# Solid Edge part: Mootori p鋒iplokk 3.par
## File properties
Author: KULL
Template: Iso Metric Part.par
Last saved by: KULL
Revision: 72
Application: Solid Edge
Density: 6920,000 kg/m^3
Accuracy: 0,990
Material: Iron, grey cast type 60
Face Style: Gray
Fill Style: ANSI31(Iron)
Virtual Style: ANSI31(Iron)
Categorization: Metals\Iron
LibraryName: Materials
Coef. of Thermal Exp: 1.1e-05
Thermal Conductivity: 48.0
Specific Heat: 544.0
Modulus of Elasticity: 158579411000.0
Poisson's Ratio: 0.29
Yield Stress: 275790291.72673446
Ultimate Stress: 413685437.59010166
Elongation: 0.0
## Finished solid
Body 1: sheet body, 1 face, 44 edges, 44 vertices.
  Faces by surface: plane 1
  Edges by curve: line 36, circle 8
Body 2: sheet body, 3 faces, 44 edges, 44 vertices.
  Faces by surface: plane 3
  Edges by curve: line 38, circle 6
Body 3: solid body, 174 faces, 446 edges, 264 vertices.
  Faces by surface: plane 98, cylinder 56, torus 20
  Edges by curve: line 302, circle 128, ellipse 16
Body 4: sheet body, 1 face, 12 edges, 12 vertices.
  Faces by surface: plane 1
  Edges by curve: line 7, circle 5
Body 5: sheet body, 1 face, 12 edges, 12 vertices.
  Faces by surface: plane 1
  Edges by curve: line 7, circle 5
Body 6: sheet body, 1 face, 12 edges, 12 vertices.
  Faces by surface: plane 1
  Edges by curve: line 7, circle 5
Body 7: sheet body, 1 face, 12 edges, 12 vertices.
  Faces by surface: plane 1
  Edges by curve: line 7, circle 5
Bounding box of the edges (mm; curved faces can reach further): 102.794 x 75.076 x 42.986, from (-51.3987, -39.4607, 37.9906) to (51.3957, 35.6155, 80.9761).
Cylindrical faces by radius (mm): R3 x2, R4 x4, R6 x14, R8 x16, R9 x16, R9.5 x2, R10 x2
Toroidal faces (ring radius, tube radius in mm): R7 r1 x10, R8.2 r0.2 x2, R9.3 r0.2 x2, R11.5 r2 x2, R18 r8 x4
Planar faces by outward normal: +x 11, +z 3, -x 11, -z 17, oblique 56
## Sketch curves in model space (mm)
line (48, 16.5423, 30.5002) -> (48, -16.5423, 30.5002)
line (48, -16.5423, 30.5002) -> (48, 16.5423, 30.5002)
circle centre (48, 0, 38.6638) radius 9.5
circle centre (48, 0, 38.6638) radius 8
circle centre (48, 0, 38.6638) radius 15.3056
line (48, -15.1609, 77.7496) -> (48, -12.5898, 74.6854)
line (48, -12.5898, 74.6854) -> (48, 12.5898, 74.6854)
line (48, 15.1609, 77.7496) -> (48, 12.5898, 74.6854)
line (48, 15.1609, 77.7496) -> (48, 35.6155, 60.5862)
line (48, 35.6155, 60.5862) -> (48, 20.5423, 42.6226)
line (48, 20.5423, 42.6226) -> (48, 20.5423, 26.5002)
line (48, 20.5423, 26.5002) -> (48, -20.5423, 26.5002)
line (48, -20.5423, 26.5002) -> (48, -20.5423, 42.6226)
line (48, -20.5423, 42.6226) -> (48, -35.6155, 60.5862)
line (48, -35.6155, 60.5862) -> (48, -15.1609, 77.7496)
line (48, 16.5423, 44.0785) -> (48, 16.5423, 30.5002)
line (48, 29.9802, 60.0931) -> (48, 16.5423, 44.0785)
line (48, 15.654, 72.1143) -> (48, 29.9802, 60.0931)
line (48, 14.455, 70.6854) -> (48, 15.654, 72.1143)
line (48, -14.455, 70.6854) -> (48, 14.455, 70.6854)
line (48, -15.654, 72.1143) -> (48, -14.455, 70.6854)
line (48, -16.5423, 30.5002) -> (48, -16.5423, 44.0785)
line (48, -16.5423, 44.0785) -> (48, -29.9802, 60.0931)
line (48, -29.9802, 60.0931) -> (48, -15.654, 72.1143)
line (48, 15.9009, 66.6854) -> (48, 24.3449, 59.6001)
line (48, 24.3449, 59.6001) -> (48, 12.5423, 45.5344)
line (48, 12.5423, 45.5344) -> (48, 12.5423, 34.5002)
line (48, 12.5423, 34.5002) -> (48, -12.5423, 34.5002)
line (48, -12.5423, 34.5002) -> (48, -12.5423, 45.5344)
line (48, -12.5423, 45.5344) -> (48, -24.3449, 59.6001)
line (48, -24.3449, 59.6001) -> (48, -15.9009, 66.6854)
line (48, -15.9009, 66.6854) -> (48, 15.9009, 66.6854)
line (48, 33.0444, 57.522) -> (-48, 33.0444, 57.522)
line (-48, 33.0444, 57.522) -> (-48, 12.5898, 74.6854)
line (-48, 12.5898, 74.6854) -> (48, 12.5898, 74.6854)
line (48, 12.5898, 74.6854) -> (48, 33.0444, 57.522)
line (48, -12.5898, 74.6854) -> (48, -33.0444, 57.522)
line (48, -33.0444, 57.522) -> (-48, -33.0444, 57.522)
line (-48, -33.0444, 57.522) -> (-48, -12.5898, 74.6854)
line (-48, -12.5898, 74.6854) -> (48, -12.5898, 74.6854)
line (0, -20.5423, 42.6226) -> (0, -20.5423, 37.4805)
line (0, -21.5469, 43.8199) -> (0, -20.5423, 42.6226)
line (0, -20.5423, 37.4805) -> (0, -18.158, 22.4349)
line (0, 20.5423, 42.6226) -> (0, 20.5423, 37.4805)
line (0, 21.5469, 43.8199) -> (0, 20.5423, 42.6226)
line (0, 20.5423, 37.4805) -> (0, 18.158, 22.4349)
line (0, -20.5423, 42.6226) -> (0, -20.5423, 37.4805)
line (0, -21.5469, 43.8199) -> (0, -20.5423, 42.6226)
line (0, -20.5423, 37.4805) -> (0, -18.158, 22.4349)
line (0, 20.5423, 42.6226) -> (0, 20.5423, 37.4805)
line (0, 21.5469, 43.8199) -> (0, 20.5423, 42.6226)
line (0, 20.5423, 37.4805) -> (0, 18.158, 22.4349)
line (0, -17.9423, 25.0349) -> (0, -12.1902, 25.0349)
line (0, -17.9423, 46.8445) -> (0, -17.9423, 25.0349)
line (0, -15.9159, 48.5449) -> (0, -17.9423, 46.8445)
line (0, -15.9159, 48.5449) -> (0, -12.1902, 25.0349)
line (0, 17.9423, 25.0349) -> (0, 12.1902, 25.0349)
line (0, 17.9423, 46.8445) -> (0, 17.9423, 25.0349)
line (0, 15.9159, 48.5449) -> (0, 17.9423, 46.8445)
line (0, -17.9423, 25.0349) -> (0, -12.1902, 25.0349)
line (0, -17.9423, 46.8445) -> (0, -17.9423, 25.0349)
line (0, -15.9159, 48.5449) -> (0, -17.9423, 46.8445)
line (0, 17.9423, 25.0349) -> (0, 12.1902, 25.0349)
line (0, 17.9423, 46.8445) -> (0, 17.9423, 25.0349)
line (0, 15.9159, 48.5449) -> (0, 17.9423, 46.8445)
line (0, 15.9159, 48.5449) -> (0, 12.1902, 25.0349)
line (0, -1.6194, 61.6114) -> (0, 1.6194, 61.6114)
line (0, -12.5898, 74.6854) -> (0, -1.6194, 61.6114)
line (0, -12.5898, 74.6854) -> (0, 12.5898, 74.6854)
circle centre (0, 0, 38.6638) radius 4
line (0, -41.2162, 67.2608) -> (0, -20.5423, 42.6226)
line (0, -41.2162, 67.2608) -> (0, -20.7617, 84.4243)
line (0, -20.7617, 84.4243) -> (0, -12.5898, 74.6854)
line (0, -21.5469, 43.8199) -> (0, -23.6514, 42.054)
line (0, -18.158, 22.4349) -> (0, -20.5423, 22.4349)
line (0, -20.5423, 22.4349) -> (0, -23.6514, 42.054)
line (0, 21.5469, 43.8199) -> (0, 23.6514, 42.054)
line (0, 18.158, 22.4349) -> (0, 20.5423, 22.4349)
line (0, 20.5423, 22.4349) -> (0, 23.6514, 42.054)
line (0, 10.4081, 72.0854) -> (0, 12.5898, 74.6854)
line (0, 1.6194, 61.6114) -> (0, 10.4081, 72.0854)
line (0, -10.9191, 72.6944) -> (0, -1.6194, 61.6114)
line (0, -1.6194, 61.6114) -> (0, -2.7629, 61.6114)
line (0, -2.7629, 61.6114) -> (0, -11.5902, 72.1314)
line (0, -11.5902, 72.1314) -> (0, -10.9191, 72.6944)
line (0, 2.7629, 61.6114) -> (0, 1.6194, 61.6114)
line (0, 11.5902, 72.1314) -> (0, 2.7629, 61.6114)
line (0, 1.6194, 61.6114) -> (0, 10.9191, 72.6944)
line (0, 10.9191, 72.6944) -> (0, 11.5902, 72.1314)
line (0, 3.8574, 53.4416) -> (0, -1.9287, 55.0599)
line (0, -1.9287, 55.0599) -> (0, -3.8574, 53.4416)
line (0, -3.8574, 53.4416) -> (0, 3.8574, 53.4416)
line (0, 2.0773, 61.6114) -> (0, -2.0773, 61.6114)
line (0, -2.0773, 61.6114) -> (0, 0, 59.1358)
line (0, 0, 59.1358) -> (0, 2.0773, 61.6114)
line (0, 0, 82.3136) -> (0, 39.108, 82.3136)
line (0, 39.108, 82.3136) -> (0, 39.108, 23.2994)
line (0, 39.108, 23.2994) -> (0, 0, 23.2994)
line (0, 0, 23.2994) -> (0, 0, 82.3136)
line (0, 0, 81.7842) -> (0, -39.844, 81.7842)
line (0, -39.844, 81.7842) -> (0, -39.844, 0)
line (0, -39.844, 0) -> (0, 0, 0)
line (0, 0, 0) -> (0, 0, 81.7842)
line (0, 41.2162, 67.2608) -> (0, 20.5423, 42.6226)
line (0, 41.2162, 67.2608) -> (0, 20.7617, 84.4243)
line (0, 20.7617, 84.4243) -> (0, 12.5898, 74.6854)
line (0, 20.5423, 42.6226) -> (0, 20.5423, 26.5002)
line (0, 20.5423, 26.5002) -> (0, 0, 26.5002)
line (0, -20.5423, 26.5002) -> (0, 0, 26.5002)
line (0, -20.5423, 42.6226) -> (0, -20.5423, 26.5002)
line (0, 12.5898, 74.6854) -> (0, 0, 74.6854)
line (0, -12.5898, 74.6854) -> (0, 0, 74.6854)
arc centre (-18, -25.3882, 69.1679) radius 9 from (-10.8482, -29.5736, 65.6559) through (-18.2666, -32.2796, 63.3853) to (-25.1518, -29.5736, 65.6559)
line (-10.8482, -29.5736, 65.6559) -> (-7.1518, -29.5736, 65.6559)
arc centre (0, -25.3882, 69.1679) radius 9 from (7.1518, -29.5736, 65.6559) through (-0.2666, -32.2796, 63.3853) to (-7.1518, -29.5736, 65.6559)
line (7.1518, -29.5736, 65.6559) -> (10.8482, -29.5736, 65.6559)
arc centre (18, -25.3882, 69.1679) radius 9 from (25.1518, -29.5736, 65.6559) through (17.7334, -32.2796, 63.3853) to (10.8482, -29.5736, 65.6559)
line (25.1518, -29.5736, 65.6559) -> (28.8482, -29.5736, 65.6559)
arc centre (36, -25.3882, 69.1679) radius 9 from (42.3572, -30.2685, 65.0728) through (35.1337, -32.2506, 63.4097) to (28.8482, -29.5736, 65.6559)
line (42.3572, -39.4607, 57.3596) -> (42.3572, -30.2685, 65.0728)
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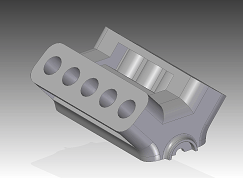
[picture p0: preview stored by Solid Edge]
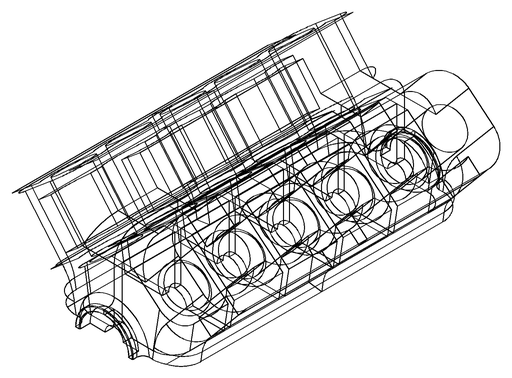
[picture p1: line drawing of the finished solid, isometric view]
